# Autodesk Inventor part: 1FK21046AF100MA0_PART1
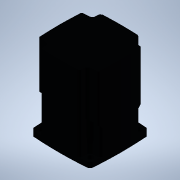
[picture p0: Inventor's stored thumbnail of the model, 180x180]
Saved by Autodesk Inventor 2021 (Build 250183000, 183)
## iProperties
Created: 2025-04
Part Number: 1FK21046AF100MA0_PART1
Material: Generic
Catalog Web Link: www.3dfindit.com
Description: -Servo synchronous motor
Document SubType Name: Modeling
Designer: psAdmin
Mass: 575.884 g
Surface Area: 489.738 cm^2
Volume: 575.884 cm^3
Density: 1 g/cm^3
Appearance: PSOLRGB-176-176-176
Category: PARTsolutions
Title: 1FK21046AF100MA0_PART1
Author: Cadenas PARTsolutions
Comments: Servo synchronous motor
Sending System: PARTsolutions
Preprocessor: ST-DEVELOPER v19.3
PSOL_IDENT_0: {$CADENAS_DATA/23d-libs/siemens_ag/_cat_/4f/2b/1fk21046af100ma0.prj},213 {VTYP=3D},{NB=1FK21046AF100
PSOL_IDENT_1: MA0_PART1},{LINA=1FK21046AF100MA0_PART1},{NN=1FK21046AF100MA0_PART1},{NOPRJ=TRUE},{DATE=19.08.2025 1
PSOL_IDENT_2: 4:00:37},{GEOMDATE=30.07.2025 02:01:06},{VERSION=},{LINEID=10},{WBVAR=},{WBNUMERIC=}  {NB=1FK21046AF
PSOL_IDENT_3: 100MA0_PART1},{LINA=1FK21046AF100MA0_PART1},{KT=DUMMY},{PREVIEW=../../../_pool_/cb/72/p_d211_xx_0043
PSOL_IDENT_4: 4j.png},{DESCSHORT=SIMOTICS S-1FK2 HD, SINAMICS S210 3AC 400V-480V, 3.2 Nm, 3000 rpm},{DESCLONG=SIMO
PSOL_IDENT_5: TICS S-1FK2 HD servo motor M0=3.2 Nm; PN = 1 kW at nN=3000 rpm (380-480 V); PN = 0.5 kW at nN=1500 r
PSOL_IDENT_6: pm (200-240 V); with holding brake; degree of protection IP64; cylindrical shaft D19x40mm; absolute
PSOL_IDENT_7: encoder 22-bit + 12-bit multiturn (encoder AM22DQC); with OCC interface; plug size M17, rotatable; S
PSOL_IDENT_8: IMOTICS S-1FK2 servomotorfor a wide range of uses in industrial environments. SIMOTICS S‑1FK2 servom
PSOL_IDENT_9: otors are compact synchronous motors with a high dynamic performance that set themselves apart as a
PSOL_IDENT_10: result of their high power density, degree of protection and overload capability. The motors are ava
PSOL_IDENT_11: ilable in two variants: as High Dynamic variant (highest dynamic performance as a result of the low
PSOL_IDENT_12: intrinsic moment of inertia for applications demanding a high dynamic performance with low moved mas
PSOL_IDENT_13: ses) - and as Compact variant (precise and stable closed-loop control for medium up to large moved m
PSOL_IDENT_14: asses as a result of a medium intrinsic moment of inertia). SIMOTICSS‑1FK2 servomotors fully exploit
PSOL_IDENT_15: their strengths in a system with the SINAMICSS210 frequency converter and simple connection using t
PSOL_IDENT_16: he one cable connection (OCC). Advantages include the short control and positioning times, fast and
PSOL_IDENT_17: precise correction of disturbing quantities as well as stable control with a high dynamic performanc
PSOL_IDENT_18: e. The servo motors can be configured to address a wide range of requirements. For example with and
PSOL_IDENT_19: without holding brake, IP64 or IP65 degree of protection, singleturn or multiturn absolute encoders
PSOL_IDENT_20: - to name just a few. Further, the servomotors are available in different shaft heights extending fr
PSOL_IDENT_21: om 20 to 100. A shaft sealing ring is available to achieve an IP65 degree of protection and for subs
PSOL_IDENT_22: equent mounting at the motor or as spare part. SIMOTICS - the optimum motor for each and every motio
PSOL_IDENT_23: n control application.},{INTNO=195125049673},{SUPPLIERALTNO=1FK2104-6AF10-0MA0},{MANUID=1FK21046AF10
PSOL_IDENT_24: 0MA0},{MANUNAME=Siemens},{MANUTYPEDESC=Synchronous motor 1FK2-HD 3.2 NM},{AAU732=SIMOTICS},{AAO057=S
PSOL_IDENT_25: -1FK2},{AAU734=SIMOTICS S-1FK2 HD servo motor M0=3.2 Nm; PN = 1 kW at nN=3000 rpm (380-480 V); PN =
PSOL_IDENT_26: 0.5 kW at nN=1500 rpm (200-240 V); with holding brake; degree of protection IP64; cylindrical shaft
PSOL_IDENT_27: D19x40mm; absolute encoder 22-bit + 12-bit multiturn (encoder AM22DQC); with OCC interface; plug siz
PSOL_IDENT_28: e M17, rotatable;},{AAW338=Synchronous motor 1FK2-HD 3.2 NM},{AAO742=SIMOTICS},{AAO663=4042948694534
PSOL_IDENT_29: },{NOCUPEROU=1},{PRICEQUANTITY=1},{QUANTITYMIN=1},{QUANTITYINT=1},{CTN=85015220},{COO=DE},{AAO676=1F
PSOL_IDENT_30: K2104-6AF10-0MA0},{AAO677=Siemens AG},{ORDERUNIT=C62},{CONTENTUNIT=C62}
NB: 1FK21046AF100MA0_PART1
NT: Servo synchronous motor
NBSYN: $MANUID._PART1
LINA: 1FK21046AF100MA0_PART1
CATALOG: SIEMENS
PREVIEW: ../../../_pool_/cb/72/p_d211_xx_00434j.png
DESCSHORT: SIMOTICS S-1FK2 HD, SINAMICS S210 3AC 400V-480V, 3.2 Nm, 3000 rpm
DESCLONG: SIMOTICS S-1FK2 HD servo motor M0=3.2 Nm; PN = 1 kW at nN=3000 rpm (380-480 V); PN = 0.5 kW at nN=1500 rpm (200-240 V); with holding brake; degree of protection
INTNO: 195125049673
SUPPLIERALTNO: 1FK2104-6AF10-0MA0
MANUID: 1FK21046AF100MA0
MANUNAME: Siemens
MANUTYPEDESC: Synchronous motor 1FK2-HD 3.2 NM
AAU732: SIMOTICS
AAO057: S-1FK2
AAU734: SIMOTICS S-1FK2 HD servo motor M0=3.2 Nm; PN = 1 kW at nN=3000 rpm (380-480 V); PN = 0.5 kW at nN=1500 rpm (200-240 V); with holding brake; degree of protection
AAW338: Synchronous motor 1FK2-HD 3.2 NM
AAO742: SIMOTICS
AAO663: 4042948694534.0
NOCUPEROU: 1
PRICEQUANTITY: 1
QUANTITYMIN: 1
QUANTITYINT: 1
CTN: 85015220
COO: DE
ARTICLENO: 1FK21046AF100MA0_PART1
BOMINFO: 1FK21046AF100MA0_PART1
CREATOR: CADENAS GmbH
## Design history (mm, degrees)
feature "2025_04_17_14_59_39_0021"
node "ECLASS_CAX_IMPORTER_001_CP_0_XY"
node "ECLASS_CAX_IMPORTER_001_CP_0_YZ"
node "ECLASS_CAX_IMPORTER_001_CP_0_ZX"
node "ECLASS_CAX_IMPORTER_001_CP_0_X"
node "ECLASS_CAX_IMPORTER_001_CP_0_Y"
node "ECLASS_CAX_IMPORTER_001_CP_0_Z"
node "ECLASS_CAX_IMPORTER_001_CP_0_Center"
node "ECLASS_CAX_IMPORTER_001_CP_1_XY"
node "ECLASS_CAX_IMPORTER_001_CP_1_YZ"
node "ECLASS_CAX_IMPORTER_001_CP_1_ZX"
node "ECLASS_CAX_IMPORTER_001_CP_1_X"
node "ECLASS_CAX_IMPORTER_001_CP_1_Y"
node "ECLASS_CAX_IMPORTER_001_CP_1_Z"
node "ECLASS_CAX_IMPORTER_001_CP_1_Center"
body "Solid1"
